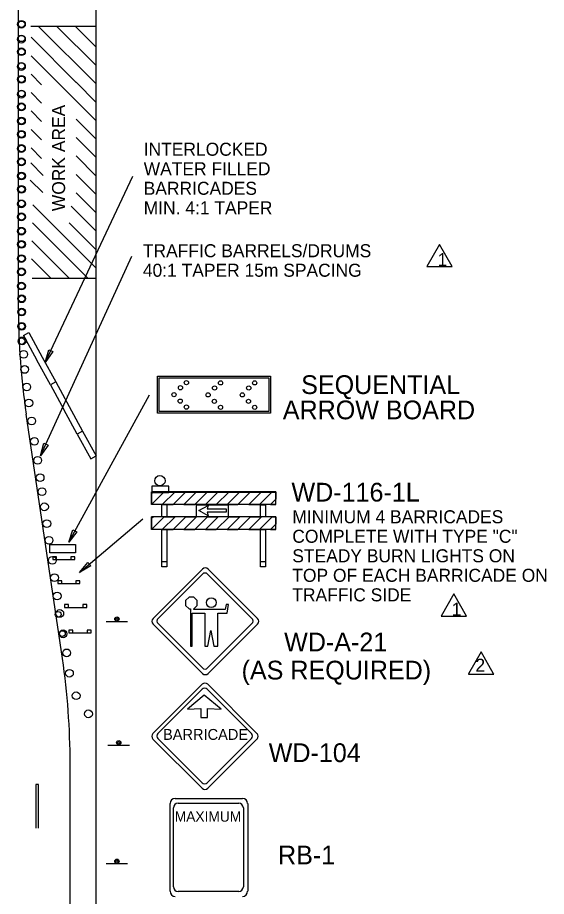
# Model space of a CAD drawing. Extents: x 2157 to 2399, y 147 to 426.
# Drawn here: x 2229.4 to 2288.3, y 269.5 to 367.4 of the extents above; entities that cross this region are included whole.
import ezdxf

# ---------------------------------------------------------------- set-up
doc = ezdxf.new("R2010")
doc.units = 0
for name, color, linetype in [('Level 1', 7, 'Continuous'), ('Level 10', 7, 'Continuous'), ('Level 20', 7, 'Continuous'), ('Level 29', 7, 'Continuous'), ('Level 44', 7, 'Continuous'), ('Level 5', 7, 'Continuous')]:
    doc.layers.add(name, color=color, linetype=linetype)

# ---------------------------------------------------------------- blocks, each defined once
blk = doc.blocks.new('REV1')
at = {"layer": 'Level 1'}
blk.add_lwpolyline([(0.114, 1.689), (-1.305, -0.781), (1.533, -0.781)], close=True, dxfattribs=at)
blk.add_text('1', height=1.448, rotation=360, dxfattribs=at).set_placement((-0.113, -0.724))

msp = doc.modelspace()

# ---------------------------------------------------------------- linework, layer by layer
at = {"layer": 'Level 1'}
for p, q in [((2248.475, 302.825), (2248.092, 302.442)), ((2249.018, 302.825), (2248.475, 302.825)), ((2249.401, 302.442), (2249.018, 302.825)), ((2248.092, 302.442), (2248.092, 301.899)), ((2248.092, 301.899), (2248.475, 301.516)), ((2249.018, 301.516), (2249.401, 301.899)), ((2249.401, 301.899), (2249.401, 302.442)), ((2252.634, 302.028), (2252.494, 301.445)), ((2252.878, 302.028), (2252.634, 302.028)), ((2252.719, 301.054), (2252.878, 302.028)), ((2248.475, 301.516), (2248.649, 301.516)), ((2248.649, 301.516), (2248.649, 297.362)), ((2248.839, 297.362), (2248.839, 301.054)), ((2248.839, 301.054), (2250.222, 301.054)), ((2249.018, 301.445), (2249.018, 301.516)), ((2252.494, 301.445), (2249.018, 301.445)), ((2250.222, 301.054), (2250.222, 297.362)), ((2251.671, 297.362), (2251.671, 301.054)), ((2251.671, 301.054), (2252.719, 301.054)), ((2250.589, 297.362), (2250.916, 299.131)), ((2250.916, 299.131), (2251.225, 297.362)), ((2248.649, 297.362), (2248.839, 297.362)), ((2250.222, 297.362), (2250.589, 297.362)), ((2251.225, 297.362), (2251.671, 297.362))]:
    msp.add_line(p, q, dxfattribs=at)
msp.add_circle((2250.951, 302.223), 0.544, dxfattribs=at)
at = {"layer": 'Level 10'}
for p, q in [((2238.136, 338.668), (2238.136, 412.512)), ((2229.476, 334.956), (2229.476, 371.499)), ((2238.136, 366.459), (2230.871, 366.459)), ((2238.136, 360.032), (2231.708, 366.459)), ((2238.136, 362.084), (2233.761, 366.459)), ((2238.136, 364.137), (2235.814, 366.459)), ((2238.136, 338.342), (2238.136, 366.459)), ((2235.922, 360.193), (2230.877, 365.237)), ((2236, 358.062), (2230.877, 363.185)), ((2232.053, 359.956), (2230.877, 361.132)), ((2238.136, 357.979), (2235.891, 360.224)), ((2232.053, 357.904), (2230.877, 359.08)), ((2238.136, 355.926), (2235.891, 358.171)), ((2232.053, 355.851), (2230.877, 357.027)), ((2238.136, 353.874), (2235.891, 356.119)), ((2232.053, 353.798), (2230.877, 354.974)), ((2238.136, 351.821), (2235.891, 354.066)), ((2232.053, 351.745), (2230.877, 352.922)), ((2238.136, 349.769), (2235.891, 352.013)), ((2232.238, 349.844), (2230.837, 351.245)), ((2232.435, 329.001), (2242.204, 349.764)), ((2238.136, 347.716), (2235.891, 349.96)), ((2232.191, 347.928), (2230.79, 349.329)), ((2238.136, 345.663), (2235.891, 347.908)), ((2238.136, 339.505), (2231.07, 346.571)), ((2238.136, 343.611), (2235.335, 346.412)), ((2237.238, 338.35), (2231.026, 344.563)), ((2238.136, 341.558), (2235.129, 344.565)), ((2235.167, 338.369), (2230.976, 342.561)), ((2233.095, 338.388), (2230.931, 340.551)), ((2231.921, 318.566), (2242.108, 340.823)), ((2238.136, 338.342), (2231.014, 338.342)), ((2238.136, 338.435), (2238.044, 338.343)), ((2238.136, 200.147), (2238.136, 338.668)), ((2233.027, 326.503), (2231.527, 329.248)), ((2232.122, 329.574), (2233.623, 326.829)), ((2233.623, 326.829), (2233.027, 326.503)), ((2235.071, 308.947), (2244.082, 325.379)), ((2236.028, 321.013), (2234.528, 323.758)), ((2235.123, 324.084), (2236.623, 321.338)), ((2234.372, 295.983), (2230.338, 323.246)), ((2236.623, 321.338), (2236.028, 321.013)), ((2236.26, 305.576), (2243.336, 311.558)), ((2235.233, 236.251), (2235.233, 284.274)), ((2231.401, 281.938), (2231.401, 277.1)), ((2231.691, 281.938), (2231.401, 281.938)), ((2231.691, 277.1), (2231.691, 281.938))]:
    msp.add_line(p, q, dxfattribs=at)
for points in [[(2233.297, 330.196), (2232.435, 329.001), (2232.84, 330.418)], [(2232.777, 319.765), (2231.921, 318.566), (2232.319, 319.984)], [(2244.33, 314.507), (2246.236, 314.507), (2246.236, 315.199), (2244.33, 315.199)], [(2235.985, 310.103), (2235.071, 308.947), (2235.538, 310.345)], [(2232.952, 308.719), (2235.813, 308.719), (2235.813, 307.765), (2232.952, 307.765)], [(2237.533, 306.319), (2236.26, 305.576), (2237.205, 306.707)]]:
    msp.add_lwpolyline(points, close=True, dxfattribs=at)
for centre, radius in [((2229.808, 366.693), 0.431), ((2229.808, 366.693), 0.359), ((2229.808, 365.024), 0.431), ((2229.808, 365.11), 0.359), ((2229.808, 363.626), 0.431), ((2229.808, 363.626), 0.359), ((2229.808, 361.981), 0.431), ((2229.808, 362.043), 0.359), ((2229.808, 360.559), 0.431), ((2229.808, 360.559), 0.359), ((2229.808, 358.889), 0.431), ((2229.809, 358.976), 0.359), ((2229.808, 357.488), 0.431), ((2229.809, 357.492), 0.359), ((2229.809, 355.909), 0.431), ((2229.809, 355.909), 0.359), ((2229.809, 354.425), 0.431), ((2229.809, 354.425), 0.359), ((2229.809, 352.841), 0.431), ((2229.809, 352.841), 0.359), ((2229.809, 351.357), 0.431), ((2229.809, 351.357), 0.359), ((2229.81, 349.774), 0.431), ((2229.81, 349.774), 0.359), ((2229.81, 348.29), 0.431), ((2229.81, 348.29), 0.359), ((2229.81, 346.667), 0.431), ((2229.81, 346.707), 0.359), ((2229.81, 345.223), 0.431), ((2229.81, 345.223), 0.359), ((2229.81, 343.623), 0.431), ((2229.81, 343.64), 0.359), ((2229.81, 342.156), 0.431), ((2229.81, 342.156), 0.359), ((2229.811, 340.573), 0.431), ((2229.811, 340.573), 0.359), ((2229.811, 339.089), 0.431), ((2229.811, 339.089), 0.359), ((2229.811, 337.505), 0.431), ((2229.811, 337.505), 0.359), ((2229.829, 336.091), 0.431), ((2229.829, 336.091), 0.359), ((2229.829, 334.607), 0.431), ((2229.829, 334.607), 0.359), ((2229.83, 333.024), 0.431), ((2229.83, 333.024), 0.359), ((2229.812, 331.371), 0.359), ((2229.895, 331.399), 0.431), ((2230.061, 329.897), 0.431), ((2230.172, 328.213), 0.431), ((2230.398, 326.26), 0.431), ((2230.632, 324.472), 0.431), ((2230.952, 322.469), 0.431), ((2231.254, 320.2), 0.431), ((2231.614, 318.082), 0.431), ((2231.887, 316.158), 0.431), ((2245.238, 315.815), 0.576), ((2232.103, 314.586), 0.431), ((2232.373, 312.9), 0.431), ((2232.632, 311.025), 0.431), ((2232.873, 309.167), 0.431), ((2233.246, 306.932), 0.431), ((2233.487, 305.001), 0.431), ((2233.786, 302.956), 0.431), ((2234.08, 301.016), 0.431), ((2234.448, 298.743), 0.431), ((2234.846, 296.619), 0.431), ((2235.156, 294.35), 0.431), ((2235.901, 291.842), 0.431), ((2237.276, 289.824), 0.431)]:
    msp.add_circle(centre, radius, dxfattribs=at)
for centre, start, end in [((2309.476, 334.956), 180, 188.41647), ((2155.233, 284.274), 0, 8.41647)]:
    msp.add_arc(centre, 80, start, end, dxfattribs=at)
at = {"layer": 'Level 20'}
for p, q in [((2230.026, 331.993), (2230.622, 332.319)), ((2230.622, 332.319), (2232.122, 329.574)), ((2230.026, 331.993), (2231.527, 329.248)), ((2233.027, 326.503), (2234.528, 323.758)), ((2233.623, 326.829), (2235.123, 324.084)), ((2236.623, 321.338), (2238.124, 318.593)), ((2236.028, 321.013), (2237.528, 318.268)), ((2237.528, 318.268), (2238.124, 318.593))]:
    msp.add_line(p, q, dxfattribs=at)
at = {"layer": 'Level 29'}
for points in [[(2281.015, 296.724), (2279.622, 294.299)], [(2282.408, 294.298), (2281.014, 296.723)], [(2279.622, 294.299), (2279.596, 294.254), (2282.435, 294.254), (2282.409, 294.299)]]:
    msp.add_lwpolyline(points, dxfattribs=at)
at = {"layer": 'Level 44'}
for p, q in [((2244.97, 323.34), (2244.97, 327.47)), ((2244.97, 327.47), (2257.551, 327.47)), ((2245.158, 323.528), (2245.158, 327.284)), ((2245.158, 327.284), (2257.363, 327.284)), ((2257.363, 327.284), (2257.363, 323.528)), ((2257.551, 327.47), (2257.551, 323.34)), ((2257.551, 323.34), (2244.97, 323.34)), ((2257.363, 323.528), (2245.158, 323.528)), ((2249.967, 305.954), (2244.473, 300.468)), ((2256.101, 300.468), (2250.616, 305.954)), ((2245.023, 300.464), (2249.967, 305.401)), ((2250.551, 305.401), (2255.489, 300.464)), ((2239.239, 300.124), (2241.635, 300.124)), ((2244.473, 299.817), (2249.967, 294.326)), ((2244.478, 299.817), (2244.473, 299.817)), ((2249.967, 294.937), (2245.023, 299.877)), ((2255.489, 299.877), (2250.551, 294.937)), ((2250.616, 294.326), (2256.101, 299.817)), ((2249.933, 293.119), (2244.455, 287.65)), ((2256.049, 287.65), (2250.58, 293.119)), ((2245.004, 287.645), (2249.933, 292.568)), ((2250.516, 292.568), (2255.439, 287.645)), ((2250.175, 291.922), (2248.292, 290.335)), ((2252.056, 290.335), (2250.175, 291.922)), ((2248.292, 290.335), (2249.797, 290.416)), ((2249.797, 290.416), (2249.797, 289.412)), ((2250.551, 289.412), (2250.551, 290.416)), ((2250.551, 290.416), (2252.056, 290.335)), ((2249.797, 289.412), (2250.547, 289.412)), ((2249.933, 282.134), (2245.004, 287.061)), ((2255.439, 287.061), (2250.516, 282.134)), ((2239.443, 286.334), (2241.839, 286.334)), ((2244.455, 287), (2249.933, 281.525)), ((2244.46, 287), (2244.455, 287)), ((2250.58, 281.525), (2256.049, 287)), ((2246.936, 280.403), (2254.432, 280.403)), ((2246.358, 270.054), (2246.358, 279.824)), ((2246.744, 270.548), (2246.744, 279.343)), ((2247.264, 279.864), (2254.01, 279.864)), ((2254.532, 279.343), (2254.532, 270.548)), ((2255.012, 279.824), (2255.012, 270.054)), ((2239.239, 273.131), (2241.635, 273.131)), ((2246.744, 270.547), (2246.744, 270.548)), ((2246.358, 270.051), (2246.358, 270.054)), ((2254.01, 270.027), (2247.264, 270.027))]:
    msp.add_line(p, q, dxfattribs=at)
for centre, radius in [((2247.521, 326.175), 0.234), ((2248.186, 326.747), 0.234), ((2251.326, 326.147), 0.234), ((2251.991, 326.718), 0.234), ((2255.131, 326.147), 0.234), ((2255.797, 326.718), 0.234), ((2246.799, 325.406), 0.234), ((2250.604, 325.378), 0.234), ((2254.41, 325.378), 0.234), ((2247.493, 324.685), 0.234), ((2251.298, 324.656), 0.234), ((2255.103, 324.656), 0.234), ((2248.186, 324.019), 0.234), ((2251.991, 323.991), 0.234), ((2255.797, 323.991), 0.234), ((2240.443, 300.393), 0.24), ((2240.443, 300.393), 0.12), ((2240.647, 286.603), 0.24), ((2240.647, 286.603), 0.12), ((2240.443, 273.4), 0.24), ((2240.443, 273.4), 0.12)]:
    msp.add_circle(centre, radius, dxfattribs=at)
for centre, radius, start, end in [((2250.29, 305.631), 0.459, 45, 135), ((2250.258, 305.11), 0.413, 45, 135), ((2244.802, 300.142), 0.459, 135, 224.99999), ((2245.318, 300.17), 0.413, 135, 224.99999), ((2255.198, 300.17), 0.413, 315, 45), ((2255.779, 300.142), 0.459, 315, 45), ((2250.258, 295.231), 0.413, 225, 315), ((2250.29, 294.654), 0.459, 225, 315), ((2250.256, 292.797), 0.458, 45, 135), ((2250.223, 292.278), 0.412, 45, 135), ((2244.783, 287.325), 0.458, 135, 224.99999), ((2245.298, 287.353), 0.412, 135, 224.99999), ((2255.149, 287.353), 0.412, 315, 45), ((2255.728, 287.325), 0.458, 315, 45), ((2250.223, 282.427), 0.412, 225, 315), ((2250.256, 281.852), 0.458, 225, 315), ((2246.937, 279.824), 0.578, 90, 179.99999), ((2254.432, 279.824), 0.578, 359.99999, 89.99999), ((2247.265, 279.342), 0.52, 90, 179.99999), ((2254.01, 279.342), 0.52, 359.99999, 89.99999), ((2247.265, 270.547), 0.52, 180, 269.99999), ((2254.01, 270.547), 0.52, 270, 359.99999), ((2246.937, 270.052), 0.578, 180, 269.99999), ((2254.432, 270.052), 0.578, 270, 359.99999)]:
    msp.add_arc(centre, radius, start, end, dxfattribs=at)
at = {"layer": 'Level 5'}
for p, q in [((2258.142, 314.563), (2244.3, 314.563)), ((2244.3, 313.144), (2244.3, 314.563)), ((2258.157, 314.535), (2244.315, 314.535)), ((2244.315, 314.535), (2258.157, 314.535)), ((2245.45, 314.535), (2245.733, 314.535)), ((2257.007, 314.563), (2256.724, 314.563)), ((2257.023, 314.535), (2256.739, 314.535)), ((2258.142, 313.144), (2258.142, 314.563)), ((2258.142, 313.144), (2244.3, 313.144)), ((2245.435, 313.117), (2245.435, 313.144)), ((2249.353, 313.13), (2252.841, 313.13)), ((2249.353, 313.13), (2252.841, 313.13)), ((2256.44, 313.117), (2256.44, 313.144)), ((2244.3, 310.38), (2244.3, 311.798)), ((2258.142, 311.798), (2244.3, 311.798)), ((2257.007, 311.798), (2256.724, 311.798)), ((2258.142, 310.38), (2258.142, 311.798)), ((2258.142, 310.38), (2244.3, 310.38)), ((2233.724, 307.33), (2233.288, 307.33)), ((2233.288, 307.33), (2233.288, 307.024)), ((2233.288, 307.024), (2235.75, 307.024)), ((2233.723, 307.025), (2233.724, 307.33)), ((2235.75, 307.33), (2235.315, 307.33)), ((2235.315, 307.33), (2235.315, 307.024)), ((2235.75, 307.024), (2235.75, 307.33)), ((2246.002, 306.763), (2245.435, 306.763)), ((2257.007, 306.763), (2256.44, 306.763)), ((2234.294, 304.665), (2233.858, 304.665)), ((2233.858, 304.665), (2233.858, 304.358)), ((2234.294, 304.359), (2234.294, 304.665)), ((2236.32, 304.665), (2235.885, 304.665)), ((2235.885, 304.665), (2235.885, 304.359)), ((2236.32, 304.359), (2236.32, 304.665)), ((2233.858, 304.358), (2236.32, 304.359)), ((2235.055, 302), (2234.619, 302)), ((2234.619, 302), (2234.619, 301.694)), ((2235.055, 301.695), (2235.055, 302)), ((2237.081, 302), (2236.646, 302)), ((2236.646, 302), (2236.646, 301.694)), ((2237.081, 301.694), (2237.081, 302)), ((2234.619, 301.694), (2237.081, 301.694)), ((2235.53, 299.144), (2235.095, 299.144)), ((2235.095, 299.144), (2235.095, 298.838)), ((2235.095, 298.838), (2237.557, 298.839)), ((2235.53, 298.839), (2235.53, 299.144)), ((2237.557, 299.144), (2237.121, 299.145)), ((2237.121, 299.144), (2237.121, 298.839)), ((2237.557, 298.839), (2237.557, 299.144))]:
    msp.add_line(p, q, dxfattribs=at)
for points in [[(2244.3, 313.144), (2245.718, 314.563), (2244.515, 314.563), (2244.3, 314.348), (2244.3, 313.144)], [(2246.707, 313.144), (2248.125, 314.563), (2246.921, 314.563), (2245.503, 313.144), (2246.707, 313.144)], [(2249.114, 313.144), (2250.532, 314.563), (2249.328, 314.563), (2247.91, 313.144), (2249.114, 313.144)], [(2251.52, 313.144), (2252.938, 314.563), (2251.735, 314.563), (2250.317, 313.144), (2251.52, 313.144)], [(2255.345, 314.563), (2254.142, 314.563), (2252.724, 313.144), (2253.927, 313.144), (2255.345, 314.563)], [(2257.752, 314.563), (2256.55, 314.563), (2255.131, 313.144), (2256.335, 313.144), (2257.752, 314.563)], [(2258.142, 313.75), (2257.537, 313.144), (2258.142, 313.144), (2258.142, 313.75)], [(2244.3, 310.38), (2245.718, 311.798), (2244.515, 311.798), (2244.3, 311.583), (2244.3, 310.38)], [(2246.707, 310.38), (2248.125, 311.798), (2246.921, 311.798), (2245.503, 310.38), (2246.707, 310.38)], [(2249.114, 310.38), (2250.532, 311.798), (2249.328, 311.798), (2247.91, 310.38), (2249.114, 310.38)], [(2251.52, 310.38), (2252.938, 311.798), (2251.735, 311.798), (2250.317, 310.38), (2251.52, 310.38)], [(2255.345, 311.798), (2254.142, 311.798), (2252.724, 310.38), (2253.927, 310.38), (2255.345, 311.798)], [(2257.752, 311.798), (2256.55, 311.798), (2255.131, 310.38), (2256.335, 310.38), (2257.752, 311.798)], [(2258.142, 310.984), (2257.537, 310.38), (2258.142, 310.38), (2258.142, 310.984)]]:
    msp.add_lwpolyline(points, dxfattribs=at)
for points in [[(2245.718, 314.563), (2246.921, 314.563), (2245.503, 313.144), (2244.3, 313.144)], [(2244.515, 314.563), (2244.3, 314.563), (2244.3, 314.348)], [(2248.125, 314.563), (2249.328, 314.563), (2247.91, 313.144), (2246.707, 313.144)], [(2250.532, 314.563), (2251.735, 314.563), (2250.317, 313.144), (2249.114, 313.144)], [(2252.938, 314.563), (2254.142, 314.563), (2252.724, 313.144), (2251.52, 313.144)], [(2255.345, 314.563), (2256.55, 314.563), (2255.131, 313.144), (2253.927, 313.144)], [(2257.752, 314.563), (2258.142, 314.563), (2258.142, 313.75), (2257.537, 313.144), (2256.335, 313.144)], [(2245.435, 313.117), (2246.002, 313.144), (2246.002, 311.798), (2245.435, 311.798)], [(2252.841, 313.13), (2252.841, 311.798), (2249.328, 311.798), (2249.328, 313.13)], [(2252.614, 312.665), (2252.614, 312.291), (2250.487, 312.291), (2250.601, 311.893), (2249.58, 312.478), (2250.601, 313.062), (2250.487, 312.665)], [(2256.44, 313.117), (2257.007, 313.117), (2257.007, 311.798), (2256.44, 311.798)], [(2244.3, 311.798), (2244.515, 311.798), (2244.3, 311.583)], [(2245.718, 311.798), (2246.921, 311.798), (2245.503, 310.38), (2244.3, 310.38)], [(2248.125, 311.798), (2249.328, 311.798), (2247.91, 310.38), (2246.707, 310.38)], [(2250.532, 311.798), (2251.735, 311.798), (2250.317, 310.38), (2249.114, 310.38)], [(2252.938, 311.798), (2254.142, 311.798), (2252.724, 310.38), (2251.52, 310.38)], [(2255.345, 311.798), (2256.55, 311.798), (2255.131, 310.38), (2253.927, 310.38)], [(2257.752, 311.798), (2258.142, 311.798), (2258.142, 310.984), (2257.537, 310.38), (2256.335, 310.38)], [(2245.435, 310.365), (2246.002, 310.365), (2246.002, 306.195), (2245.435, 306.195)], [(2256.44, 310.365), (2257.007, 310.365), (2257.007, 306.195), (2256.44, 306.195)]]:
    msp.add_lwpolyline(points, close=True, dxfattribs=at)
for centre in [(2233.899, 300.916), (2234.373, 298.768)]:
    msp.add_circle(centre, 0.323, dxfattribs=at)

# ---------------------------------------------------------------- block references
at = {"layer": 'Level 10'}
for p in [(2276.276, 340.452), (2277.864, 301.496)]:
    msp.add_blockref('REV1', p, dxfattribs=at)

# ---------------------------------------------------------------- texts
for s, height, rotation, p in [('WORK AREA', 1.4514, 90, (2234.673, 345.856)), ('SEQUENTIAL', 2.09, 0, (2260.972, 325.473)), ('ARROW BOARD', 2.08999, 0, (2258.925, 322.658)), ('2', 1.448, 360, (2280.388, 294.523))]:
    msp.add_text(s, height=height, rotation=rotation, dxfattribs=at).set_placement(p)
for s, height, p in [('INTERLOCKED', 1.4514, (2243.429, 352.033)), ('WATER FILLED', 1.4514, (2243.429, 349.856)), ('BARRICADES', 1.4514, (2243.429, 347.68)), ('MIN. 4:1 TAPER', 1.4514, (2243.429, 345.503)), ('TRAFFIC BARRELS/DRUMS ', 1.4514, (2243.334, 340.721)), ('40:1 TAPER 15m SPACING', 1.4514, (2243.334, 338.545)), ('WD-116-1L', 2.09, (2259.891, 313.488)), ('MINIMUM 4 BARRICADES', 1.4514, (2259.984, 311.068)), ('COMPLETE WITH TYPE "C" ', 1.4514, (2259.984, 308.892)), ('STEADY BURN LIGHTS ON ', 1.4514, (2259.984, 306.716)), ('TOP OF EACH BARRICADE ON ', 1.4514, (2259.984, 304.54)), ('TRAFFIC SIDE', 1.4514, (2259.984, 302.364)), ('WD-A-21', 2.09, (2259.073, 296.789)), ('(AS REQUIRED)', 2.09001, (2254.333, 293.655)), ('WD-104', 2.09, (2257.357, 284.45)), ('RB-1', 2.09, (2258.394, 273.044))]:
    msp.add_text(s, height=height, dxfattribs=at).set_placement(p)
at = {"layer": 'Level 44'}
for s, height, p in [('BARRICADE', 1.2144, (2245.581, 286.924)), ('MAXIMUM', 1.1467, (2246.886, 277.805))]:
    msp.add_text(s, height=height, rotation=360, dxfattribs=at).set_placement(p)

doc.saveas('drawing.dxf')
